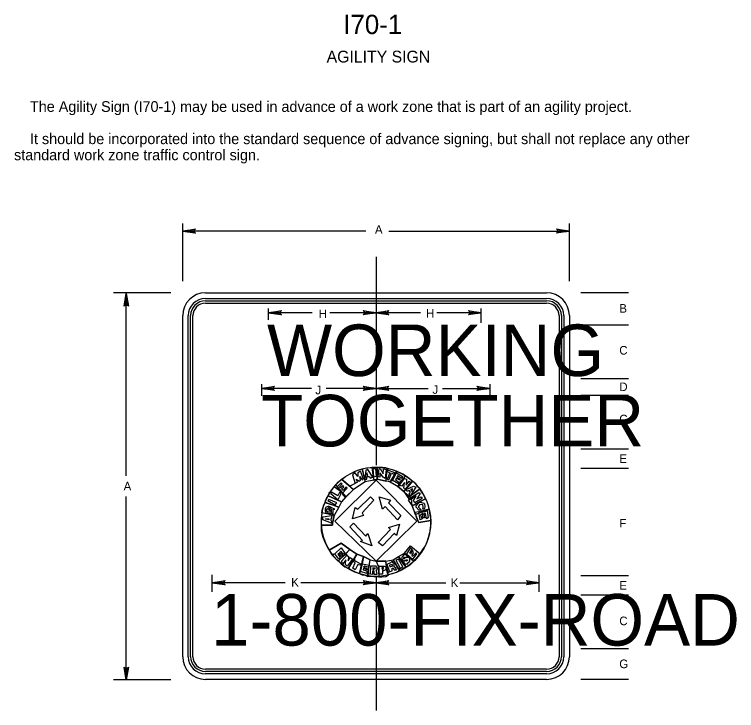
# Model space of a CAD drawing. Extents: x 0.013 to 0.194, y 0.004 to 0.259.
# Drawn here: x 0.0256 to 0.1937, y 0.0971 to 0.2592 of the extents above; entities that cross this region are included whole.
import ezdxf

# ---------------------------------------------------------------- set-up
doc = ezdxf.new("R2010")
doc.units = 0
for name, color, linetype in [('1', 7, 'Continuous'), ('2', 7, 'Continuous'), ('3', 7, 'Continuous')]:
    doc.layers.add(name, color=color, linetype=linetype)

# ---------------------------------------------------------------- blocks, each defined once
blk = doc.blocks.new('RARROW')
at = {"layer": '3'}
for p, q in [((-2.156, 0.285), (-2.2665, 0.384625)), ((-2.2665, 0.384625), (0, 0)), ((0, 0), (-2.2665, -0.379125)), ((-2.156, 0.285), (-2.075625, 0.12075)), ((0, 0), (-2.156, 0.285)), ((-2.14975, -0.2705), (0, 0)), ((-2.075625, 0.12075), (0, 0)), ((0, 0), (-2.074, -0.108)), ((-2.2665, -0.379125), (-2.14975, -0.2705)), ((-2.074, -0.108), (-2.14975, -0.2705))]:
    blk.add_line(p, q, dxfattribs=at)

msp = doc.modelspace()

# ---------------------------------------------------------------- linework, layer by layer
at = {"layer": '1'}
for points in [[(0.10175, 0.151), (0.10263, 0.15163), (0.10375, 0.15225), (0.10487, 0.15288), (0.106, 0.15325), (0.1065, 0.15338), (0.10725, 0.15038), (0.1045, 0.14863), (0.10363, 0.14938), (0.1055, 0.15038), (0.10512, 0.151), (0.10587, 0.1505), (0.10612, 0.15075), (0.106, 0.15163), (0.1065, 0.15088), (0.10687, 0.151), (0.10612, 0.15288), (0.1055, 0.1525), (0.1055, 0.15163), (0.10487, 0.1525), (0.10425, 0.152), (0.10487, 0.15), (0.10363, 0.14938)], [(0.1065, 0.15338), (0.1075, 0.15363), (0.10837, 0.15375), (0.10875, 0.15375), (0.10925, 0.15075), (0.10725, 0.15038), (0.10712, 0.151), (0.10762, 0.151), (0.10762, 0.15163), (0.10825, 0.15163), (0.10837, 0.15125), (0.109, 0.1515), (0.10787, 0.15325), (0.10737, 0.15313), (0.10712, 0.151), (0.10712, 0.151)], [(0.10925, 0.15075), (0.11, 0.151), (0.11, 0.15375), (0.10912, 0.15375), (0.10875, 0.15375), (0.10912, 0.1515), (0.10925, 0.15163), (0.10912, 0.1535), (0.10963, 0.1535), (0.10975, 0.15163), (0.10912, 0.1515)], [(0.11, 0.151), (0.11213, 0.1505), (0.11238, 0.1535), (0.112, 0.15363), (0.11125, 0.15375), (0.1105, 0.15375), (0.11, 0.15375), (0.11, 0.15163), (0.11025, 0.15163), (0.1105, 0.1535), (0.11075, 0.1535), (0.11138, 0.15225), (0.1115, 0.15338), (0.11213, 0.15325), (0.11188, 0.15113), (0.11138, 0.1515), (0.11063, 0.1525), (0.11063, 0.1515), (0.11, 0.15163)], [(0.11238, 0.1535), (0.11288, 0.15338), (0.1135, 0.15325), (0.114, 0.15313), (0.1145, 0.15288), (0.113, 0.15038), (0.11213, 0.1505), (0.11213, 0.15113), (0.11275, 0.15088), (0.11338, 0.15238), (0.114, 0.15213), (0.11413, 0.1525), (0.1125, 0.15313), (0.11238, 0.15275), (0.113, 0.1525), (0.11238, 0.151), (0.11213, 0.15113)], [(0.10762, 0.15188), (0.10787, 0.15188), (0.10762, 0.1525)], [(0.113, 0.15038), (0.115, 0.14925), (0.11663, 0.15175), (0.116, 0.15213), (0.11538, 0.1525), (0.115, 0.15263), (0.1145, 0.15288), (0.113, 0.15038), (0.11363, 0.15075), (0.1145, 0.1525), (0.11588, 0.15163), (0.11575, 0.15113), (0.11475, 0.15175), (0.11463, 0.1515), (0.11538, 0.151), (0.11525, 0.15075), (0.1145, 0.15125), (0.11425, 0.15088), (0.115, 0.15038), (0.115, 0.14988), (0.1135, 0.15075), (0.1135, 0.15075)], [(0.11475, 0.14938), (0.11625, 0.14813), (0.11825, 0.1505), (0.11775, 0.15088), (0.1175, 0.15113), (0.11688, 0.15163), (0.11663, 0.15175), (0.115, 0.14988), (0.11513, 0.1495), (0.11638, 0.15113), (0.11688, 0.151), (0.11675, 0.14963), (0.1175, 0.1505), (0.11775, 0.15025), (0.11663, 0.14875), (0.11625, 0.14888), (0.11638, 0.15025), (0.11575, 0.14938), (0.115, 0.14963)], [(0.097, 0.14025), (0.097, 0.139), (0.09738, 0.1375), (0.098, 0.136), (0.09863, 0.13475), (0.09888, 0.1345), (0.10163, 0.13612), (0.10363, 0.13462), (0.10525, 0.1335), (0.10687, 0.133), (0.10837, 0.13225), (0.10975, 0.13187), (0.10013, 0.14125), (0.10975, 0.15075), (0.11, 0.151), (0.10925, 0.15075), (0.10725, 0.15038), (0.1045, 0.14863), (0.10275, 0.14688), (0.10175, 0.14575), (0.10113, 0.1445), (0.1, 0.1425), (0.09963, 0.14075), (0.09963, 0.14025)], [(0.09863, 0.14713), (0.09888, 0.14775), (0.099, 0.148), (0.09938, 0.14838), (0.09975, 0.14888), (0.10038, 0.14963), (0.10275, 0.14688), (0.10175, 0.14575), (0.10088, 0.14613), (0.10163, 0.14763), (0.10125, 0.14788), (0.10088, 0.14713), (0.09938, 0.148), (0.09925, 0.14763), (0.10088, 0.14625), (0.10088, 0.14613)], [(0.1, 0.14925), (0.1005, 0.14975), (0.101, 0.15038), (0.10175, 0.151), (0.1045, 0.14863), (0.10263, 0.14675), (0.10188, 0.14763), (0.103, 0.14888), (0.10275, 0.14913), (0.10213, 0.14838), (0.10175, 0.14875), (0.10225, 0.14925), (0.102, 0.1495), (0.1015, 0.149), (0.10125, 0.14925), (0.10188, 0.14988), (0.10163, 0.15013), (0.10063, 0.14913), (0.102, 0.14775), (0.10213, 0.14763)], [(0.10975, 0.15075), (0.11925, 0.14125), (0.10975, 0.13187), (0.10013, 0.14125)], [(0.10975, 0.15075), (0.11925, 0.14125), (0.10975, 0.13187), (0.112, 0.13187), (0.11375, 0.13225), (0.115, 0.133), (0.11638, 0.13375), (0.11775, 0.1355), (0.12, 0.13362), (0.12062, 0.13462), (0.12125, 0.1355), (0.12187, 0.137), (0.12225, 0.13837), (0.1225, 0.14025), (0.1225, 0.14125), (0.1225, 0.14138), (0.11975, 0.14088), (0.11875, 0.14325), (0.11813, 0.14475), (0.118, 0.1465), (0.11625, 0.14813), (0.11475, 0.14938), (0.113, 0.15038), (0.11213, 0.1505), (0.11, 0.151)], [(0.11625, 0.14813), (0.11713, 0.14675), (0.12, 0.14875), (0.1195, 0.14925), (0.119, 0.14988), (0.11825, 0.1505), (0.11675, 0.14875), (0.11675, 0.14863), (0.1185, 0.14938), (0.119, 0.14913), (0.11763, 0.147), (0.1175, 0.1475), (0.11775, 0.148), (0.1175, 0.14838), (0.117, 0.14813), (0.11675, 0.14875)], [(0.11725, 0.14613), (0.11813, 0.14475), (0.12125, 0.14638), (0.121, 0.147), (0.12062, 0.14763), (0.12025, 0.14813), (0.12, 0.14875), (0.11713, 0.14675), (0.11738, 0.14638), (0.11975, 0.14788), (0.12, 0.14763), (0.11925, 0.14638), (0.12025, 0.14688), (0.1205, 0.1465), (0.11875, 0.1455), (0.1185, 0.146), (0.11913, 0.14713), (0.11825, 0.1465), (0.11813, 0.14638)], [(0.11775, 0.14863), (0.11813, 0.14813), (0.11825, 0.14875)], [(0.09788, 0.1455), (0.098, 0.146), (0.09825, 0.1465), (0.09863, 0.14713), (0.10175, 0.14575), (0.10113, 0.1445), (0.10013, 0.14475), (0.10025, 0.145), (0.10063, 0.1455), (0.09875, 0.14625), (0.0985, 0.146), (0.10025, 0.145), (0.10013, 0.14475)], [(0.10425, 0.14175), (0.10487, 0.14438), (0.1055, 0.144), (0.1085, 0.14688), (0.10925, 0.14613), (0.1065, 0.14313), (0.10687, 0.1425)], [(0.1105, 0.14688), (0.11313, 0.14613), (0.11263, 0.1455), (0.1155, 0.1425), (0.11475, 0.1415), (0.11188, 0.14463), (0.11125, 0.144)], [(0.11813, 0.14475), (0.11888, 0.14275), (0.12212, 0.144), (0.122, 0.14475), (0.12175, 0.1455), (0.1215, 0.14613), (0.12125, 0.14638), (0.11975, 0.14563), (0.11975, 0.1455), (0.12, 0.14563), (0.12012, 0.14563), (0.12062, 0.1455), (0.12087, 0.14538), (0.121, 0.14525), (0.12112, 0.14463), (0.121, 0.14413), (0.12087, 0.144), (0.12062, 0.144), (0.12075, 0.14438), (0.12075, 0.14463), (0.12062, 0.145), (0.1205, 0.14513), (0.12062, 0.145), (0.12025, 0.14513), (0.11988, 0.145), (0.11963, 0.14463), (0.11963, 0.1445), (0.11963, 0.1445), (0.11988, 0.14425), (0.12025, 0.14388), (0.12, 0.14375), (0.11975, 0.14375), (0.1195, 0.144), (0.11938, 0.14413), (0.11913, 0.1445), (0.11913, 0.14475), (0.11963, 0.14538), (0.11975, 0.1455), (0.11975, 0.1455), (0.11975, 0.14563)], [(0.09713, 0.14313), (0.09725, 0.14375), (0.09738, 0.14425), (0.09763, 0.145), (0.09788, 0.14563), (0.10113, 0.1445), (0.1, 0.1425), (0.0995, 0.14313), (0.09975, 0.14325), (0.09975, 0.14363), (0.09975, 0.14388), (0.09975, 0.144), (0.10013, 0.144), (0.09875, 0.14463), (0.0985, 0.14463), (0.098, 0.14438), (0.09788, 0.144), (0.09788, 0.14375), (0.098, 0.14325), (0.09825, 0.14313), (0.09875, 0.143), (0.09925, 0.143), (0.0995, 0.14313), (0.1, 0.1425)], [(0.09888, 0.14463), (0.09875, 0.14438), (0.0985, 0.14413), (0.0985, 0.144), (0.09825, 0.144), (0.09825, 0.14363), (0.0985, 0.14338), (0.09863, 0.14338), (0.09888, 0.14338), (0.09925, 0.14338), (0.09938, 0.14338), (0.09938, 0.14375), (0.09938, 0.144), (0.09925, 0.144), (0.09925, 0.14363), (0.09875, 0.14375), (0.09925, 0.1445)], [(0.09713, 0.14313), (0.097, 0.14175), (0.097, 0.14025), (0.09963, 0.14025), (0.09963, 0.14075), (0.09938, 0.14075), (0.09738, 0.1415), (0.09738, 0.14225), (0.0995, 0.1425), (0.09938, 0.142), (0.09925, 0.14175), (0.09925, 0.14138), (0.09938, 0.14125), (0.09938, 0.14075), (0.09963, 0.14075), (0.1, 0.1425), (0.09713, 0.14313), (0.09713, 0.14313)], [(0.11875, 0.14325), (0.11925, 0.14175), (0.11975, 0.14088), (0.1225, 0.14138), (0.1225, 0.142), (0.12237, 0.1425), (0.12225, 0.14325), (0.12212, 0.144), (0.11975, 0.14338), (0.11975, 0.14313), (0.12162, 0.14363), (0.12187, 0.142), (0.1215, 0.14175), (0.12125, 0.143), (0.12087, 0.143), (0.121, 0.142), (0.12062, 0.142), (0.12062, 0.143), (0.12012, 0.14263), (0.1205, 0.14175), (0.12, 0.1415), (0.11975, 0.14338)], [(0.09875, 0.14175), (0.09875, 0.1415), (0.098, 0.14175)], [(0.10875, 0.1355), (0.10612, 0.1365), (0.10662, 0.13675), (0.10363, 0.13987), (0.1045, 0.14075), (0.10737, 0.13775), (0.10787, 0.13837)], [(0.11525, 0.1405), (0.1145, 0.13787), (0.114, 0.13837), (0.11125, 0.1355), (0.11025, 0.13625), (0.11313, 0.13925), (0.11263, 0.13975)], [(0.0995, 0.13337), (0.1, 0.13287), (0.1005, 0.13237), (0.101, 0.132), (0.10363, 0.13462), (0.10163, 0.13612), (0.09888, 0.1345), (0.09925, 0.13375), (0.0995, 0.13337), (0.10013, 0.13362), (0.10163, 0.135), (0.1025, 0.13375), (0.10213, 0.1335), (0.10163, 0.13412), (0.10125, 0.13387), (0.102, 0.13337), (0.10163, 0.133), (0.10113, 0.13375), (0.10088, 0.1335), (0.10138, 0.13275), (0.10113, 0.13237), (0.10013, 0.13362)], [(0.101, 0.132), (0.10163, 0.13125), (0.102, 0.131), (0.1025, 0.13062), (0.10338, 0.13025), (0.10525, 0.1335), (0.10363, 0.13462), (0.10263, 0.1335), (0.10338, 0.133), (0.10325, 0.132), (0.10375, 0.13275), (0.10425, 0.13237), (0.103, 0.13075), (0.10263, 0.13112), (0.10275, 0.13225), (0.102, 0.13125), (0.10175, 0.13187), (0.103, 0.13337), (0.10263, 0.1335)], [(0.11638, 0.13375), (0.11775, 0.1355), (0.12, 0.13362), (0.11975, 0.13337), (0.11925, 0.13275), (0.11875, 0.13225), (0.1185, 0.132), (0.11825, 0.13225), (0.11925, 0.13362), (0.11913, 0.13387), (0.11825, 0.133), (0.11813, 0.13337), (0.1185, 0.13387), (0.11825, 0.1345), (0.11775, 0.13362), (0.11763, 0.13375), (0.11813, 0.13462), (0.11775, 0.135), (0.11688, 0.13362), (0.11825, 0.13237), (0.11825, 0.13225)], [(0.10338, 0.13025), (0.104, 0.12987), (0.10475, 0.1295), (0.10587, 0.129), (0.10687, 0.133), (0.10525, 0.1335), (0.1045, 0.13225), (0.10612, 0.13125), (0.10587, 0.131), (0.1055, 0.13112), (0.10487, 0.12987), (0.10437, 0.13025), (0.10487, 0.1315), (0.10437, 0.13187), (0.10487, 0.13225), (0.1045, 0.13225)], [(0.10587, 0.129), (0.1065, 0.12875), (0.10725, 0.12862), (0.10787, 0.12837), (0.10837, 0.13225), (0.10687, 0.133), (0.1065, 0.13125), (0.10825, 0.131), (0.10787, 0.1305), (0.10712, 0.13075), (0.10687, 0.1305), (0.10762, 0.13025), (0.10762, 0.12987), (0.10687, 0.13025), (0.10675, 0.12987), (0.10762, 0.12962), (0.10762, 0.129), (0.10612, 0.1295), (0.10662, 0.13125), (0.1065, 0.13125)], [(0.11375, 0.13225), (0.115, 0.133), (0.11675, 0.1305), (0.11625, 0.13025), (0.11575, 0.12987), (0.11525, 0.12975), (0.115, 0.13), (0.116, 0.13062), (0.115, 0.13237), (0.11438, 0.13212), (0.11538, 0.13025), (0.115, 0.13)], [(0.115, 0.133), (0.11638, 0.13375), (0.1185, 0.132), (0.11813, 0.1315), (0.11763, 0.131), (0.117, 0.13062), (0.11675, 0.1305), (0.11625, 0.13112), (0.11638, 0.13125), (0.11688, 0.13125), (0.11713, 0.13125), (0.11713, 0.1315), (0.11763, 0.13187), (0.11763, 0.13212), (0.11763, 0.13262), (0.11713, 0.13275), (0.11688, 0.13275), (0.11663, 0.13275), (0.11625, 0.13237), (0.11625, 0.13275), (0.11625, 0.13275), (0.11625, 0.13275), (0.11638, 0.13287), (0.11638, 0.13287), (0.11663, 0.13275), (0.11675, 0.13275), (0.117, 0.133), (0.11688, 0.13337), (0.11638, 0.13337), (0.11625, 0.13337), (0.11588, 0.133), (0.11588, 0.133), (0.11575, 0.13287), (0.11575, 0.13275), (0.11575, 0.13237), (0.11588, 0.13212), (0.11625, 0.132), (0.11663, 0.13212), (0.11688, 0.13225), (0.117, 0.13225), (0.11713, 0.13212), (0.11688, 0.13187), (0.11688, 0.13187), (0.11663, 0.132), (0.11625, 0.13187), (0.11625, 0.1315), (0.11638, 0.13125), (0.11625, 0.13112)], [(0.10837, 0.13225), (0.10975, 0.13187), (0.11025, 0.13075), (0.11038, 0.12825), (0.10975, 0.12825), (0.10925, 0.12825), (0.10837, 0.12837), (0.10787, 0.12837), (0.10787, 0.129), (0.109, 0.12887), (0.109, 0.12962), (0.10925, 0.12962), (0.10925, 0.1295), (0.10925, 0.12887), (0.11, 0.12887), (0.10988, 0.12962), (0.10975, 0.12987), (0.11, 0.12987), (0.11, 0.13025), (0.10975, 0.13075), (0.1095, 0.13075), (0.109, 0.13075), (0.1085, 0.13075), (0.10837, 0.12887), (0.10787, 0.129)], [(0.11038, 0.12825), (0.11113, 0.12825), (0.112, 0.12837), (0.11263, 0.12875), (0.112, 0.13187), (0.10975, 0.13187), (0.11025, 0.13075), (0.11025, 0.13075), (0.11138, 0.13075), (0.11163, 0.13075), (0.112, 0.13062), (0.112, 0.13025), (0.112, 0.13), (0.112, 0.12987), (0.1115, 0.12962), (0.11125, 0.12962), (0.11125, 0.12887), (0.1105, 0.12887), (0.1105, 0.13075), (0.11025, 0.13075)], [(0.112, 0.13187), (0.11375, 0.13225), (0.11525, 0.12975), (0.1145, 0.12925), (0.11363, 0.129), (0.11263, 0.12875), (0.11238, 0.12925), (0.1135, 0.12962), (0.1135, 0.13025), (0.11363, 0.13025), (0.11375, 0.13025), (0.114, 0.12987), (0.114, 0.12987), (0.1145, 0.12987), (0.11438, 0.13025), (0.114, 0.13062), (0.114, 0.13075), (0.114, 0.131), (0.114, 0.13112), (0.114, 0.13125), (0.11375, 0.1315), (0.1135, 0.13187), (0.11313, 0.1315), (0.11225, 0.13112), (0.11288, 0.1295), (0.11238, 0.12925)], [(0.11288, 0.131), (0.113, 0.13062), (0.1135, 0.13075), (0.1135, 0.13075), (0.11363, 0.131), (0.1135, 0.131), (0.1135, 0.13112), (0.1135, 0.13112)], [(0.109, 0.13037), (0.109, 0.13), (0.10925, 0.13), (0.1095, 0.13025), (0.10963, 0.13025), (0.10963, 0.13025), (0.1095, 0.13025), (0.10925, 0.13025)], [(0.11113, 0.13037), (0.11125, 0.12987), (0.11138, 0.13), (0.1115, 0.13025), (0.1115, 0.13025), (0.1115, 0.13025), (0.1115, 0.13025), (0.11138, 0.1305), (0.11125, 0.1305)]]:
    msp.add_lwpolyline(points, close=True, dxfattribs=at)
msp.add_circle((0.10976, 0.14108), 0.01271, dxfattribs=at)
at = {"layer": '3'}
for p, q in [((0.06475, 0.19712), (0.06475, 0.2105)), ((0.15475, 0.19712), (0.15475, 0.2105)), ((0.10737, 0.20875), (0.06475, 0.20875)), ((0.11275, 0.20875), (0.15475, 0.20875)), ((0.10975, 0.20275), (0.10975, 0.15425)), ((0.062, 0.19437), (0.04863, 0.19437)), ((0.05163, 0.15175), (0.05163, 0.19437)), ((0.07005, 0.19437), (0.14945, 0.19437)), ((0.1685, 0.19437), (0.15738, 0.19437)), ((0.07005, 0.19307), (0.14945, 0.19307)), ((0.07005, 0.19252), (0.14945, 0.19252)), ((0.07005, 0.19197), (0.14945, 0.19197)), ((0.08475, 0.18812), (0.08475, 0.19074)), ((0.13425, 0.18737), (0.13425, 0.19074)), ((0.06475, 0.10967), (0.06475, 0.18907)), ((0.06605, 0.10967), (0.06605, 0.18907)), ((0.0666, 0.10967), (0.0666, 0.18907)), ((0.06715, 0.10967), (0.06715, 0.18907)), ((0.09488, 0.18974), (0.08475, 0.18974)), ((0.10975, 0.18974), (0.099, 0.18974)), ((0.12012, 0.18974), (0.10975, 0.18974)), ((0.13425, 0.18974), (0.12387, 0.18974)), ((0.15235, 0.18907), (0.15235, 0.10967)), ((0.1529, 0.18907), (0.1529, 0.10967)), ((0.15345, 0.18907), (0.15345, 0.10967)), ((0.15475, 0.18907), (0.15475, 0.10967)), ((0.1685, 0.18688), (0.15738, 0.18688)), ((0.08313, 0.17313), (0.08313, 0.17037)), ((0.13625, 0.17313), (0.13625, 0.17037)), ((0.1685, 0.17438), (0.15738, 0.17438)), ((0.09475, 0.17213), (0.08313, 0.17213)), ((0.10975, 0.17213), (0.09813, 0.17213)), ((0.10975, 0.17213), (0.12187, 0.17213)), ((0.12525, 0.17213), (0.13625, 0.17213)), ((0.1685, 0.1705), (0.15738, 0.1705)), ((0.1685, 0.158), (0.15738, 0.158)), ((0.1685, 0.1535), (0.15738, 0.1535)), ((0.05163, 0.10437), (0.05163, 0.147)), ((0.07163, 0.12475), (0.07163, 0.12875)), ((0.10975, 0.12825), (0.10975, 0.09713)), ((0.14775, 0.12475), (0.14775, 0.12875)), ((0.1685, 0.1285), (0.15738, 0.1285)), ((0.08862, 0.12688), (0.07163, 0.12688)), ((0.10975, 0.12688), (0.09225, 0.12688)), ((0.10975, 0.12688), (0.126, 0.12688)), ((0.12925, 0.12688), (0.14775, 0.12688)), ((0.1685, 0.124), (0.15738, 0.124)), ((0.1685, 0.1115), (0.15738, 0.1115)), ((0.14945, 0.10678), (0.07005, 0.10678)), ((0.14945, 0.10623), (0.07005, 0.10623)), ((0.062, 0.10425), (0.04863, 0.10425)), ((0.14945, 0.10568), (0.07005, 0.10568)), ((0.14945, 0.10437), (0.07005, 0.10437)), ((0.1685, 0.10437), (0.15738, 0.10437))]:
    msp.add_line(p, q, dxfattribs=at)
for centre, radius, start, end in [((0.07005, 0.18907), 0.0053, 90, 180), ((0.14945, 0.18907), 0.0053, 0, 90), ((0.07005, 0.18907), 0.004, 90, 180), ((0.07005, 0.18907), 0.00345, 90, 180), ((0.07005, 0.18907), 0.0029, 90, 180), ((0.14945, 0.18907), 0.004, 0, 90), ((0.14945, 0.18907), 0.00345, 0, 90), ((0.14945, 0.18907), 0.0029, 0, 90), ((0.07005, 0.10967), 0.0053, 180, 270), ((0.07005, 0.10967), 0.004, 180, 270), ((0.07005, 0.10967), 0.00345, 180, 270), ((0.07005, 0.10967), 0.0029, 180, 270), ((0.14945, 0.10967), 0.0053, 270, 0), ((0.14945, 0.10967), 0.004, 270, 0), ((0.14945, 0.10967), 0.00345, 270, 0), ((0.14945, 0.10967), 0.0029, 270, 0)]:
    msp.add_arc(centre, radius, start, end, dxfattribs=at)

# ---------------------------------------------------------------- block references
at = {"layer": '3', "xscale": 0.0013236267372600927, "yscale": 0.001309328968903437}
for p, rotation in [((0.06475, 0.20875), 180), ((0.05163, 0.19425), 89.99999999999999), ((0.08475, 0.18974), 180), ((0.10975, 0.18974), 180), ((0.08313, 0.17213), 180), ((0.10975, 0.17213), 180), ((0.07163, 0.12688), 180), ((0.10975, 0.12688), 180), ((0.05163, 0.10425), -90.00000000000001)]:
    msp.add_blockref('RARROW', p, dxfattribs=dict(at, rotation=rotation))
for p in [(0.15475, 0.20875), (0.10975, 0.18974), (0.13425, 0.18974), (0.10975, 0.17213), (0.13625, 0.17213), (0.10975, 0.12688), (0.14775, 0.12688)]:
    msp.add_blockref('RARROW', p, dxfattribs=at)

# ---------------------------------------------------------------- texts
at = {"layer": '1'}
for s, height, p in [('I70-1', 0.0045, (0.10213, 0.25462)), ('AGILITY SIGN', 0.0027503, (0.09825, 0.248)), ('WORKING', 0.012, (0.08438, 0.175)), ('TOGETHER', 0.012, (0.083, 0.15863)), ('1-800-FIX-ROAD', 0.012, (0.07138, 0.11225))]:
    msp.add_text(s, height=height, dxfattribs=at).set_placement(p)
at = {"layer": '2'}
for s, height, p in [('    The Agility Sign (I70-1) may be used in advance of a work zone that is part of an agility project.', 0.00249975, (0.0255, 0.2365)), ('    It should be incorporated into the standard sequence of advance signing, but shall not replace any other', 0.00249975, (0.0255, 0.229)), ('standard work zone traffic control sign.', 0.0024998, (0.0255, 0.22525))]:
    msp.add_text(s, height=height, dxfattribs=at).set_placement(p)
at = {"layer": '3'}
for s, p in [('A', (0.1095, 0.20813)), ('B', (0.16637, 0.18975)), ('H', (0.09638, 0.18849)), ('H', (0.12137, 0.18862)), ('C', (0.16637, 0.18)), ('D', (0.16637, 0.1715)), ('J', (0.09563, 0.17075)), ('J', (0.12287, 0.17087)), ('C', (0.16637, 0.164)), ('E', (0.16637, 0.15475)), ('A', (0.051, 0.14838)), ('F', (0.16637, 0.13975)), ('K', (0.09, 0.126)), ('K', (0.12713, 0.12588)), ('E', (0.16637, 0.12525)), ('C', (0.16637, 0.117)), ('G', (0.16637, 0.107))]:
    msp.add_text(s, height=0.002, dxfattribs=at).set_placement(p)

doc.saveas('drawing.dxf')
